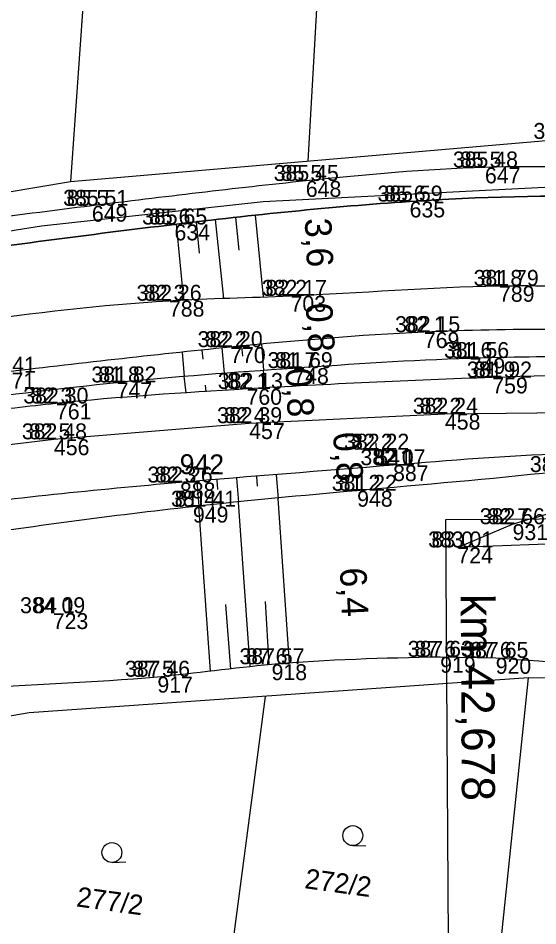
# Model space of a CAD drawing. Extents: x -514509 to -512782, y -1144610 to -1143439.
# Drawn here: x -513195.4 to -513156.2, y -1143623.8 to -1143555.3 of the extents above; entities that cross this region are included whole.
import ezdxf

# ---------------------------------------------------------------- set-up
doc = ezdxf.new("R2010")
doc.units = 0
for name, color, linetype in [('Vrstva 1', 7, 'Continuous'), ('Vrstva 10', 7, 'Continuous'), ('Vrstva 11', 7, 'Continuous'), ('Vrstva 12', 7, 'Continuous'), ('Vrstva 38', 7, 'Continuous'), ('Vrstva 39', 7, 'Continuous'), ('Vrstva 57', 7, 'Continuous'), ('Vrstva 58', 7, 'Continuous'), ('Vrstva 59', 7, 'Continuous'), ('Vrstva 6', 7, 'Continuous'), ('Vrstva 60', 7, 'Continuous'), ('Vrstva 8', 7, 'Continuous'), ('Vrstva 9', 7, 'Continuous')]:
    doc.layers.add(name, color=color, linetype=linetype)

msp = doc.modelspace()

# ---------------------------------------------------------------- linework, layer by layer
at = {"layer": 'Vrstva 1'}
msp.add_lwpolyline([(-513220.491, -1143575.228), (-513193.623, -1143570.982), (-513176.915, -1143569.129), (-513155.694, -1143568.05), (-513138.074, -1143568.989), (-513122.982, -1143570.739), (-513098.68, -1143574.346), (-513082.799, -1143577.731), (-513077.892, -1143579.384), (-513072.257, -1143581.789), (-513063.773, -1143586.163), (-513056.631, -1143588.823), (-513045.948, -1143590.353), (-513035.79, -1143591.42), (-513027.577, -1143592.226), (-513018.616, -1143594.003), (-513003.093, -1143598.799), (-512994.741, -1143602.979), (-512987.23, -1143608.317)], dxfattribs=at)
at = {"layer": 'Vrstva 10'}
for points in [[(-513582.696, -1143761.24), (-513581.966, -1143752.218), (-513543.007, -1143722.265), (-513536.98, -1143726.125), (-513503.11, -1143701.59), (-513467.163, -1143704.368), (-513409.406, -1143670.068), (-513367.763, -1143641.182), (-513337.875, -1143622.14), (-513302.677, -1143606.244), (-513297.569, -1143595.846), (-513289.461, -1143596.696), (-513287.694, -1143584.666), (-513262.147, -1143588.316), (-513251.067, -1143584.844), (-513248.39, -1143579.25), (-513218.784, -1143572.229), (-513191.434, -1143567.629), (-513154.1, -1143564.42), (-513082.649, -1143574.448)], [(-513582.696, -1143761.24), (-513581.966, -1143752.218), (-513543.007, -1143722.265), (-513536.98, -1143726.125), (-513503.11, -1143701.59), (-513467.163, -1143704.368), (-513409.406, -1143670.068), (-513367.763, -1143641.182), (-513337.875, -1143622.14), (-513302.677, -1143606.244), (-513297.569, -1143595.846), (-513289.461, -1143596.696), (-513287.694, -1143584.666), (-513262.147, -1143588.316), (-513251.067, -1143584.844), (-513248.39, -1143579.25), (-513218.784, -1143572.229), (-513191.434, -1143567.629), (-513154.1, -1143564.42), (-513082.649, -1143574.448)], [(-513180.515, -1143570.503), (-513179.9, -1143576.455)], [(-513179.003, -1143570.335), (-513178.748, -1143572.809)], [(-513177.498, -1143570.168), (-513176.897, -1143576.335)], [(-513183.459, -1143570.853), (-513182.903, -1143576.574)], [(-513181.966, -1143570.698), (-513181.74, -1143573.03)], [(-513180.013, -1143580.185), (-513179.851, -1143582.081)], [(-513178.544, -1143580.052), (-513178.466, -1143580.793)], [(-513177.033, -1143579.871), (-513176.867, -1143581.86)], [(-513183.021, -1143580.523), (-513182.849, -1143582.312)], [(-513181.518, -1143580.35), (-513181.456, -1143581.031)], [(-513179.706, -1143583.362), (-513179.851, -1143582.081)], [(-513176.753, -1143583.202), (-513176.867, -1143581.86)], [(-513182.699, -1143583.566), (-513182.849, -1143582.312)], [(-513181.2, -1143583.488), (-513181.242, -1143582.989)], [(-513178.206, -1143583.277), (-513178.253, -1143582.741)], [(-513175.921, -1143589.757), (-513175.777, -1143591.525)], [(-513181.901, -1143590.243), (-513181.75, -1143592.106)], [(-513180.406, -1143590.122), (-513180.347, -1143590.857)], [(-513178.911, -1143590), (-513178.764, -1143591.815)], [(-513177.416, -1143589.878), (-513177.358, -1143590.595)], [(-513177.895, -1143604.213), (-513178.764, -1143591.815)], [(-513174.911, -1143603.959), (-513175.776, -1143591.525)], [(-513180.879, -1143604.541), (-513181.75, -1143592.106)], [(-513152.824, -1143594.864), (-513162.263, -1143595.224), (-513158.104, -1143593.473)], [(-513176.442, -1143604.032), (-513176.732, -1143599.291)], [(-513179.348, -1143604.395), (-513179.723, -1143599.533)], [(-513083.73, -1143602.284), (-513086.215, -1143618.123), (-513093.877, -1143618.167), (-513107.772, -1143623.787), (-513104.437, -1143605.443), (-513156.888, -1143605.053), (-513194.553, -1143607.705), (-513250.415, -1143617.382), (-513252.832, -1143634.619), (-513276.036, -1143634.192), (-513293.984, -1143635.345), (-513297.884, -1143620.719), (-513339.729, -1143642.048), (-513370.62, -1143660.746), (-513392.287, -1143677.542), (-513448.783, -1143734.317), (-513496.135, -1143770.535), (-513525.567, -1143795.084), (-513571.166, -1143828.084), (-513591.968, -1143845.266)], [(-513083.73, -1143602.284), (-513086.215, -1143618.123), (-513093.877, -1143618.167), (-513107.772, -1143623.787), (-513104.437, -1143605.443), (-513156.888, -1143605.053), (-513194.553, -1143607.705), (-513250.415, -1143617.382), (-513252.832, -1143634.619), (-513276.036, -1143634.192), (-513293.984, -1143635.345), (-513297.884, -1143620.719), (-513339.729, -1143642.048), (-513370.62, -1143660.746), (-513392.287, -1143677.542), (-513448.783, -1143734.317), (-513496.135, -1143770.535), (-513525.567, -1143795.084), (-513571.166, -1143828.084), (-513591.968, -1143845.266)], [(-513163.564, -1143603.466), (-513159.373, -1143603.548)]]:
    msp.add_lwpolyline(points, dxfattribs=at)
for points in [[(-513123.946, -1143569.095), (-513136.959, -1143567.384), (-513147.544, -1143566.738), (-513160.182, -1143566.568), (-513173.688, -1143567.587), (-513189.822, -1143569.464), (-513207.783, -1143571.88), (-513222.493, -1143574.402), (-513233.063, -1143576.666), (-513241.875, -1143578.979), (-513244.418, -1143579.885), (-513245.683, -1143580.636), (-513246.818, -1143581.512), (-513247.979, -1143582.57), (-513250.194, -1143584.261), (-513254.387, -1143586.238), (-513258.899, -1143587.657), (-513263.404, -1143588.363), (-513269.418, -1143588.55), (-513272.851, -1143588.177)], [(-513257.245, -1143589.431), (-513254.229, -1143588.505), (-513250.102, -1143586.392), (-513247.476, -1143584.933), (-513245.605, -1143583.389), (-513244.222, -1143582.217), (-513242.919, -1143581.425), (-513240.929, -1143580.476), (-513238.55, -1143579.701), (-513235.633, -1143579.04), (-513227.79, -1143577.445), (-513216.392, -1143575.319), (-513202.945, -1143573.374), (-513183.589, -1143570.866), (-513165.858, -1143569.141), (-513150.059, -1143568.836), (-513140.147, -1143569.606), (-513128.565, -1143571.075), (-513110.146, -1143573.354)], [(-513110.146, -1143573.354), (-513128.565, -1143571.075), (-513140.147, -1143569.606), (-513150.059, -1143568.836), (-513165.858, -1143569.141), (-513183.589, -1143570.866), (-513202.945, -1143573.374), (-513216.392, -1143575.319), (-513227.79, -1143577.445), (-513235.633, -1143579.04), (-513238.55, -1143579.701), (-513240.929, -1143580.476), (-513242.919, -1143581.425), (-513244.222, -1143582.217), (-513245.605, -1143583.389), (-513247.476, -1143584.933), (-513250.102, -1143586.392), (-513254.229, -1143588.505), (-513257.245, -1143589.431)], [(-513214.733, -1143584.448), (-513229.213, -1143586.91), (-513238.6, -1143588.453), (-513241.201, -1143588.819), (-513242.494, -1143588.658), (-513242.951, -1143588.231), (-513243.264, -1143587.589), (-513243.39, -1143586.875), (-513242.873, -1143586.302), (-513241.47, -1143585.565), (-513237.994, -1143584.65), (-513226.616, -1143582.332), (-513214.669, -1143580.21), (-513199.307, -1143578.201), (-513184.01, -1143576.618), (-513174.841, -1143576.254), (-513159.12, -1143575.498), (-513141.488, -1143576.138)], [(-513126.688, -1143579.693), (-513145.166, -1143578.936), (-513164.792, -1143578.992), (-513179.394, -1143580.122), (-513196.779, -1143582.049)], [(-513207.806, -1143584.902), (-513200.104, -1143584.163), (-513187.953, -1143582.78), (-513174.631, -1143581.697), (-513161.331, -1143580.944), (-513143.415, -1143580.927), (-513126.935, -1143581.459), (-513113.185, -1143582.581)], [(-513125.346, -1143582.991), (-513142.773, -1143582.22), (-513159.634, -1143582.409), (-513178.161, -1143583.275), (-513192.534, -1143584.371), (-513198.723, -1143585.08)], [(-513105.656, -1143589.572), (-513111.398, -1143588.825), (-513120.896, -1143588.124), (-513127.781, -1143587.815), (-513134.493, -1143587.399), (-513145.289, -1143587.917), (-513154.263, -1143588.165), (-513167.107, -1143589.025), (-513183.18, -1143590.33), (-513202.182, -1143592.368), (-513213.364, -1143594.183), (-513223.359, -1143596.374), (-513234.22, -1143598.682), (-513248.131, -1143602.316), (-513262.889, -1143606.569), (-513272.412, -1143609.783), (-513278.746, -1143612.526), (-513284.257, -1143615.463), (-513287.251, -1143617.25), (-513289.125, -1143618.716), (-513289.862, -1143619.586), (-513289.805, -1143620.367), (-513289.601, -1143620.971)], [(-513125.264, -1143589.045), (-513135.661, -1143588.368), (-513143.283, -1143588.407), (-513146.019, -1143588.597), (-513154.875, -1143589.536), (-513169.823, -1143590.946), (-513182.203, -1143592.15), (-513200.496, -1143594.572), (-513221.669, -1143598.242), (-513242.802, -1143603.101), (-513261.502, -1143608.166), (-513271.576, -1143611.724), (-513278.023, -1143614.872), (-513282.94, -1143617.541)], [(-513158.104, -1143593.473), (-513148.789, -1143590.929), (-513143.894, -1143590.098), (-513138.244, -1143589.971), (-513131.901, -1143590.434), (-513119.953, -1143591.147), (-513108.601, -1143592.503)], [(-513288.864, -1143622.334), (-513288.741, -1143623.077), (-513288.298, -1143623.643), (-513287.721, -1143623.716), (-513286.782, -1143623.652), (-513285.36, -1143623.174), (-513280.172, -1143621.177), (-513273.312, -1143618.728), (-513265.846, -1143616.567), (-513258.497, -1143615.884), (-513247.208, -1143613.96), (-513233.331, -1143611.288), (-513215.215, -1143608.159), (-513199.36, -1143605.934), (-513184.883, -1143604.971), (-513176.269, -1143604.031), (-513163.564, -1143603.466)], [(-513159.373, -1143603.548), (-513146.3, -1143604.299), (-513130.687, -1143604.173), (-513118.12, -1143604.088)]]:
    msp.add_spline(points, degree=3, dxfattribs=at)
at = {"layer": 'Vrstva 12'}
for p, q in [((-513168.407, -1143587.355), (-513168.362, -1143588.354)), ((-513168.884, -1143587.877), (-513167.885, -1143587.832))]:
    msp.add_line(p, q, dxfattribs=at)
at = {"layer": 'Vrstva 38'}
msp.add_lwpolyline([(-513145.4, -1143593.023), (-513163.146, -1143593.136), (-513162.802, -1143648.559)], dxfattribs=at)
at = {"layer": 'Vrstva 6'}
msp.add_lwpolyline([(-513208.28, -1143588.89), (-513206.53, -1143588.73), (-513192.68, -1143587.07), (-513177.96, -1143585.85), (-513163.2, -1143585.14), (-513147.003, -1143584.986), (-513133.476, -1143585.281), (-513125.836, -1143585.708)], dxfattribs=at)
at = {"layer": 'Vrstva 60'}
for p, q in [((-513160.18, -1143566.57), (-513160.18, -1143566.57)), ((-513173.69, -1143567.59), (-513173.69, -1143567.59)), ((-513165.86, -1143569.14), (-513165.86, -1143569.14)), ((-513189.82, -1143569.46), (-513189.82, -1143569.46)), ((-513183.59, -1143570.87), (-513183.59, -1143570.87)), ((-513159.12, -1143575.5), (-513159.12, -1143575.5)), ((-513184.01, -1143576.62), (-513184.01, -1143576.62)), ((-513174.84, -1143576.25), (-513174.84, -1143576.25)), ((-513164.79, -1143578.99), (-513164.79, -1143578.99)), ((-513179.39, -1143580.12), (-513179.39, -1143580.12)), ((-513161.33, -1143580.94), (-513161.33, -1143580.94)), ((-513174.63, -1143581.7), (-513174.63, -1143581.7)), ((-513187.95, -1143582.78), (-513187.95, -1143582.78)), ((-513159.63, -1143582.41), (-513159.63, -1143582.41)), ((-513178.16, -1143583.27), (-513178.16, -1143583.27)), ((-513192.53, -1143584.37), (-513192.53, -1143584.37)), ((-513163.2, -1143585.14), (-513163.2, -1143585.14)), ((-513177.96, -1143585.85), (-513177.96, -1143585.85)), ((-513192.68, -1143587.07), (-513192.68, -1143587.07)), ((-513168.38, -1143587.85), (-513168.38, -1143587.85)), ((-513167.11, -1143589.02), (-513167.11, -1143589.02)), ((-513183.18, -1143590.33), (-513183.18, -1143590.33)), ((-513169.82, -1143590.95), (-513169.82, -1143590.95)), ((-513182.2, -1143592.15), (-513182.2, -1143592.15)), ((-513158.1, -1143593.47), (-513158.1, -1143593.47)), ((-513162.26, -1143595.22), (-513162.26, -1143595.22)), ((-513192.77, -1143600.18), (-513192.77, -1143600.18)), ((-513163.56, -1143603.47), (-513163.56, -1143603.47)), ((-513176.27, -1143604.03), (-513176.27, -1143604.03)), ((-513159.37, -1143603.55), (-513159.37, -1143603.55)), ((-513184.88, -1143604.97), (-513184.88, -1143604.97))]:
    msp.add_line(p, q, dxfattribs=at)
at = {"layer": 'Vrstva 8'}
for p, q in [((-513188.029, -1143519.148), (-513191.434, -1143567.629)), ((-513170.934, -1143519.353), (-513173.531, -1143566.091)), ((-513160.798, -1143642.595), (-513156.888, -1143605.053)), ((-513176.744, -1143606.452), (-513181.413, -1143641.631))]:
    msp.add_line(p, q, dxfattribs=at)
at = {"layer": 'Vrstva 9'}
for p, q in [((-513170.153, -1143617.701), (-513169.154, -1143617.713)), ((-513188.264, -1143618.978), (-513187.266, -1143618.919))]:
    msp.add_line(p, q, dxfattribs=at)
for centre in [(-513170.144, -1143616.951), (-513188.309, -1143618.229)]:
    msp.add_circle(centre, 0.75, dxfattribs=at)

# ---------------------------------------------------------------- texts
at = {"layer": 'Vrstva 11'}
for s, height, rotation, p in [('3,6', 2, 272.69692, (-513173.771, -1143570.421)), ('0,8', 2, 273.4441, (-513173.703, -1143576.846)), ('0,8', 2, 272.65208, (-513175.221, -1143581.729)), ('0,8', 2, 275.43534, (-513171.661, -1143586.616)), ('942', 1.5, 359.71622, (-513183.202, -1143589.696)), ('6,4', 2, 272.4887, (-513171.119, -1143596.774))]:
    msp.add_text(s, height=height, rotation=rotation, dxfattribs=at).set_placement(p)
at = {"layer": 'Vrstva 39'}
msp.add_text('km 42,678', height=2.5, rotation=270.35509, dxfattribs=at).set_placement((-513162.014, -1143598.738))
at = {"layer": 'Vrstva 57'}
for s, p in [('85 5 ', (-513162.063, -1143566.57)), ('85 5 ', (-513175.573, -1143567.59)), ('85 6 ', (-513167.784, -1143569.14)), ('85 5 ', (-513191.703, -1143569.46)), ('85 6 ', (-513185.514, -1143570.87)), ('81 8 ', (-513160.493, -1143575.5)), ('82 3 ', (-513185.893, -1143576.62)), ('82 2 ', (-513176.723, -1143576.25)), ('82 1 ', (-513166.248, -1143578.99)), ('82 2 ', (-513181.273, -1143580.12)), ('81 6 ', (-513162.744, -1143580.94)), ('81 7 ', (-513176.003, -1143581.7)), ('81 8 ', (-513189.323, -1143582.78)), ('81 9 ', (-513161.008, -1143582.41)), ('82 1 ', (-513179.618, -1143583.27)), ('82 3 ', (-513194.413, -1143584.37)), ('82 2 ', (-513165.083, -1143585.14)), ('82 4 ', (-513179.843, -1143585.85)), ('82 5 ', (-513194.563, -1143587.07)), ('82 2 ', (-513170.263, -1143587.85)), ('82 1 ', (-513168.568, -1143589.02)), ('82 3 ', (-513185.063, -1143590.33)), ('81 2 ', (-513171.193, -1143590.95)), ('81 4 ', (-513183.573, -1143592.15)), ('82 7 ', (-513159.983, -1143593.47)), ('83 0 ', (-513164.208, -1143595.22)), ('84 1 ', (-513194.228, -1143600.18)), ('87 6 ', (-513178.194, -1143604.03)), ('87 6 ', (-513165.484, -1143603.47)), ('87 6 ', (-513161.294, -1143603.55)), ('87 5 ', (-513186.763, -1143604.97))]:
    msp.add_text(s, height=1.2, dxfattribs=at).set_placement(p)
at = {"layer": 'Vrstva 58'}
for s, p in [('385 49', (-513156.524, -1143564.42)), ('385 48', (-513162.601, -1143566.57)), ('385 45', (-513176.111, -1143567.59)), ('385 59', (-513168.284, -1143569.14)), ('385 51', (-513191.986, -1143569.46)), ('385 65', (-513186.036, -1143570.87)), ('381 79', (-513161.034, -1143575.5)), ('382 26', (-513186.456, -1143576.62)), ('382 17', (-513177.006, -1143576.25)), ('382 15', (-513166.956, -1143578.99)), ('382 20', (-513181.85, -1143580.12)), ('381 56', (-513163.266, -1143580.94)), ('382 41', (-513198.946, -1143582.05)), ('381 69', (-513176.57, -1143581.7)), ('381 82', (-513189.861, -1143582.78)), ('381 92', (-513161.544, -1143582.41)), ('382 13', (-513180.326, -1143583.27)), ('382 30', (-513194.99, -1143584.37)), ('382 24', (-513165.621, -1143585.14)), ('382 39', (-513180.384, -1143585.85)), ('382 48', (-513195.101, -1143587.07)), ('382 22', (-513170.801, -1143587.85)), ('382 07', (-513169.57, -1143589.02)), ('381 28', (-513156.791, -1143589.54)), ('382 26', (-513185.626, -1143590.33)), ('381 22', (-513171.731, -1143590.95)), ('381 41', (-513183.856, -1143592.15)), ('382 66', (-513160.57, -1143593.47)), ('383 01', (-513164.465, -1143595.22)), ('384 09', (-513195.233, -1143600.18)), ('387 57', (-513178.691, -1143604.03)), ('387 63', (-513166.006, -1143603.47)), ('387 65', (-513161.816, -1143603.55)), ('387 46', (-513187.326, -1143604.97))]:
    msp.add_text(s, height=1.2, dxfattribs=at).set_placement(p)
at = {"layer": 'Vrstva 59'}
for s, p in [('647', (-513160.18, -1143567.77)), ('648', (-513173.69, -1143568.79)), ('635', (-513165.86, -1143570.34)), ('649', (-513189.82, -1143570.66)), ('634', (-513183.59, -1143572.07)), ('789', (-513159.12, -1143576.7)), ('788', (-513184.01, -1143577.82)), ('703', (-513174.84, -1143577.45)), ('769', (-513164.79, -1143580.19)), ('770', (-513179.39, -1143581.32)), ('749', (-513161.33, -1143582.14)), ('771', (-513196.78, -1143583.25)), ('748', (-513174.63, -1143582.9)), ('747', (-513187.95, -1143583.98)), ('759', (-513159.63, -1143583.61)), ('760', (-513178.16, -1143584.47)), ('761', (-513192.53, -1143585.57)), ('458', (-513163.2, -1143586.34)), ('457', (-513177.96, -1143587.05)), ('456', (-513192.68, -1143588.27)), ('541', (-513168.38, -1143589.05)), ('887', (-513167.11, -1143590.22)), ('888', (-513183.18, -1143591.53)), ('948', (-513169.82, -1143592.15)), ('949', (-513182.2, -1143593.35)), ('931', (-513158.1, -1143594.67)), ('724', (-513162.26, -1143596.42)), ('723', (-513192.77, -1143601.38)), ('919', (-513163.56, -1143604.67)), ('918', (-513176.27, -1143605.23)), ('920', (-513159.37, -1143604.75)), ('917', (-513184.88, -1143606.17))]:
    msp.add_text(s, height=1.2, dxfattribs=at).set_placement(p)
at = {"layer": 'Vrstva 9'}
for s, p in [('272/2', (-513173.831, -1143620.91)), ('277/2', (-513191.038, -1143622.284))]:
    msp.add_text(s, height=1.5, rotation=352.22933, dxfattribs=at).set_placement(p)

doc.saveas('drawing.dxf')
